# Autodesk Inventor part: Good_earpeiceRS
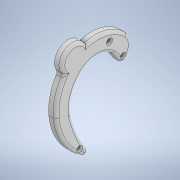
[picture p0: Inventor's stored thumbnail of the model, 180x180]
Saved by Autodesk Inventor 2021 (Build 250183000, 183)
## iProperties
Created: 2021-02
Part Number: Good_earpeiceRS
Material: Generic
Document SubType Name: Modeling
Designer: callu
Density: 1 g/cm^3
Appearance: Default
Author: callu
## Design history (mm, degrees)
sketch "Sketch2" dims "d26" = 0, "d27" = 0
  geometry: L1 (-25.305, 31.037)-(-25.305, 31.017); L2 (-14.045, -3.328)-(-14.045, -3.328); A1 r 27.085 centre (-15.75, 12.927) between (3.057, -6.564) and (10.201, 20.68); A2 r 34.213 centre (-20.037, 7.225) between (-0.462, 35.285) and (-23.063, 41.304); A3 r 15.394 centre (-15.456, 13.46) between (-3.961, 3.221) and (-5.132, 24.879); A4 r 24.822 centre (-21.779, 6.467) between (-5.132, 24.879) and (-25.305, 31.037); A5 r 9.689 centre (-3.671, 0.409) between (-12.797, -2.847) and (3.057, -6.564); A6 r 175.968 centre (-86.315, 157.028) between (-12.797, -2.847) and (-12.017, -2.486); A7 r 37.952 centre (-29.739, 31.074) between (-12.017, -2.486) and (-3.961, 3.221); A8 r 84.854 centre (-5.465, -51.465) between (-25.305, 31.037) and (-57.408, 15.633); A9 r 40.798 centre (-19.454, 0.666) between (-23.063, 41.304) and (-57.408, 15.633); A10 r 9.074 centre (5.493, 28.437) between (10.201, 20.68) and (-0.462, 35.285); 5 further points
  constraints: 21 point on circle, 10 centre point, 4 end point, 3 tangent, 12 other
extrude "Extrusion3" new body sketch "Sketch2" distance "d28" = 5; taper "d29" = 0 deg
fillet "Fillet4" dims "d41" = 2
fillet "Fillet6" dims "d62" = 2
sketch "Sketch6"
  geometry: L1 (35.285, -0.996)-(23.285, -0.996); L2 (23.285, -0.996)-(23.285, 9.004); L3 (23.285, 9.004)-(35.285, 9.004); L4 (35.285, 9.004)-(35.285, -0.996); 2 further points
  constraints: 8 end point, 2 parallel, 1 horizontal, 1 perpendicular
  dimensions: "d63" = 12 distance of L2.end L3.end; "d64" = 10 distance of L1.end L2.end; "d65" = 0.534 distance of L1.start point (35.285, -0.462)
extrude "Extrusion7" cut sketch "Sketch6" distance "d66" = 1; taper "d67" = 0 deg
fillet "Fillet7" dims "d68" = 2.5
fillet "Fillet8" dims "d69" = 0.5
sketch "Sketch7"
  geometry: C1 r 4 at (-3.591, -2.868); A1 r 9.689 centre (0.409, -3.671) between (-6.564, 3.057) and (-4.821, -11.827) reference; 1 further point
  constraints: 1 centre point
  dimensions: "d70" = 8 diameter of C1; "d71" = 4 horizontal distance of A1.centre C1.centre
extrude "Extrusion8" cut sketch "Sketch7" distance "d72" = 2; taper "d73" = 0 deg
sketch "Sketch8"
  geometry: 4 further points
  dimensions: "d74" = 3.75 horizontal distance of point (3.75, -8.5) point (0, 0); "d75" = 8.5 vertical distance of point (0, 0) point (3.75, -8.5); "d76" = 5.5 horizontal distance of point (0, 0) point (-5.5, 4.5); "d77" = 4.5 vertical distance of point (0, 0) point (-5.5, 4.5); "d78" = 25.5 horizontal distance of point (0, 0) point (-25.5, -48); "d79" = 48 vertical distance of point (-25.5, -48) point (0, 0)
hole "Hole1" sketch "Sketch8" at (3.75, -8.5), (-5.5, 4.5), (-25.5, -48) diameter "d80" = 2; stored, may be unused: countersink angle "d84" = 90 deg, drill point angle "d86" = 118 deg; dims "d81" = 5.98424, "d82" = 4, "d83" = 2, "d85" = 8
body "Solid3"
